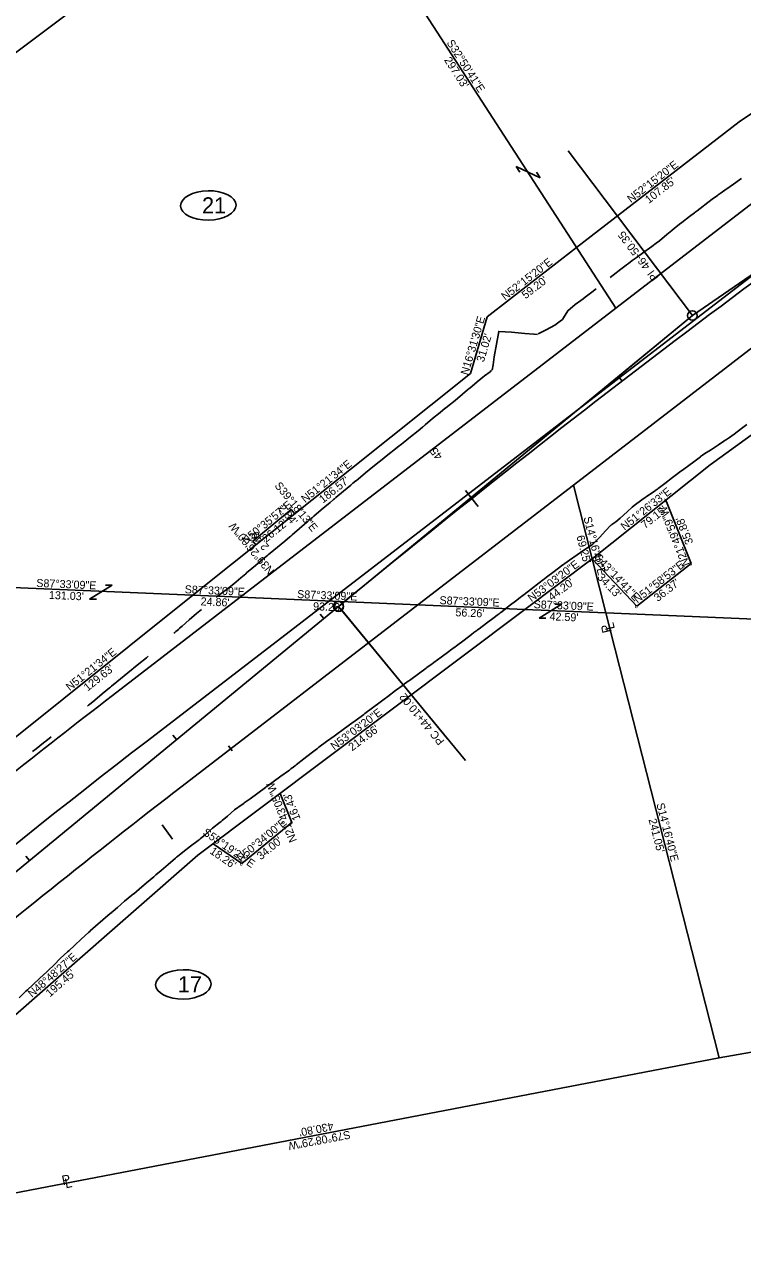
# Model space of a CAD drawing. Extents: x 1145508 to 2262867, y -3126236 to 2021677.
# Drawn here: x 1147661 to 1148038, y 2017346 to 2017985 of the extents above; entities that cross this region are included whole.
import ezdxf

# ---------------------------------------------------------------- set-up
doc = ezdxf.new("R2010")
doc.units = 0
for name, color, linetype in [('Default', 7, 'Continuous'), ('DSN_DRFT_Guideline-No-Plot', 7, 'Continuous'), ('DSN_RDWY_Alignment', 7, 'Continuous'), ('DSN_RDWY_Alignment Annotation', 7, 'Continuous'), ('DSN_RDWY_Const Limits', 7, 'Continuous'), ('DSN_ROW_Annotation', 7, 'Continuous'), ('DSN_ROW_Esmnt', 7, 'Continuous'), ('DSN_ROW_Line', 7, 'Continuous'), ('DSN_ROW_Line-Annotation', 7, 'Continuous'), ('DSN_ROW_Prop-Line', 7, 'Continuous'), ('DSN_ROW_Prop-Line-Annotation', 7, 'Continuous'), ('E_Const Align', 7, 'Continuous'), ('EX_QSECTION', 7, 'Continuous'), ('EX_ROW', 7, 'Continuous'), ('EX_ROW_ANNOT', 7, 'Continuous'), ('EX_SIGN', 7, 'Continuous')]:
    doc.layers.add(name, color=color, linetype=linetype)

msp = doc.modelspace()

# ---------------------------------------------------------------- linework, layer by layer
at = {"layer": 'Default'}
msp.add_line((1148336.03, 2018078.83), (1147725.18, 2017608.51), dxfattribs=at)
msp.add_arc((1150521.47, 2013976.61), 4583.66, 127.59365, 131.75523, dxfattribs=at)
at = {"layer": 'DSN_RDWY_Alignment'}
for p, q in [((1148011.14, 2017831.73), (1148208.89, 2017968.31)), ((1147825.51, 2017679.08), (1148011.14, 2017831.73))]:
    msp.add_line(p, q, dxfattribs=at)
for points in [[(1148011.14, 2017831.73), (1147945.95, 2017918.14)], [(1147825.51, 2017679.08), (1147892.09, 2017598.12)]]:
    msp.add_lwpolyline(points, dxfattribs=at)
for centre in [(1148011.14, 2017831.73), (1147825.51, 2017679.08)]:
    msp.add_circle(centre, 2.5, dxfattribs=at)
at = {"layer": 'DSN_RDWY_Alignment Annotation'}
for p, q in [((1148011.14, 2017831.73), (1147975, 2017879.63)), ((1147975, 2017879.63), (1147975, 2017879.63)), ((1148011.14, 2017831.73), (1148070.38, 2017872.65)), ((1148011.14, 2017831.73), (1147955.52, 2017786)), ((1147972.39, 2017799.68), (1147974.22, 2017797.3)), ((1147892.13, 2017739.86), (1147898.75, 2017731.56)), ((1147825.51, 2017679.08), (1147825.51, 2017679.08)), ((1147827.21, 2017677.02), (1147882.68, 2017609.57)), ((1147815.87, 2017675.03), (1147817.77, 2017672.72)), ((1147738.63, 2017611.52), (1147740.54, 2017609.2)), ((1147882.68, 2017609.57), (1147882.68, 2017609.57)), ((1147661.4, 2017548), (1147663.3, 2017545.68))]:
    msp.add_line(p, q, dxfattribs=at)
msp.add_circle((1147825.51, 2017679.08), 2.67, dxfattribs=at)
at = {"layer": 'DSN_RDWY_Const Limits'}
for points in [[(1147968.02, 2017851.67), (1147969.59, 2017852.97), (1147973.59, 2017856.04), (1147976.33, 2017858.15), (1147976.51, 2017858.28), (1147977.59, 2017859.11), (1147979.56, 2017860.62), (1147981.65, 2017862.09), (1147985.74, 2017865.05), (1147988.57, 2017867.1), (1147988.68, 2017867.18), (1147989.82, 2017868.01), (1147992.23, 2017869.76), (1147993.88, 2017870.99), (1147997.77, 2017874.22), (1148000.42, 2017876.43), (1148000.58, 2017876.56), (1148001.64, 2017877.45), (1148004.32, 2017879.68), (1148005.54, 2017880.65), (1148009.58, 2017883.66), (1148012.26, 2017885.71), (1148012.55, 2017885.93), (1148013.59, 2017886.73), (1148016.75, 2017889.14), (1148017.6, 2017889.79), (1148021.6, 2017892.85), (1148024.32, 2017894.82), (1148024.62, 2017895.03), (1148025.7, 2017895.79), (1148029.36, 2017898.37), (1148029.82, 2017898.69), (1148033.94, 2017901.6), (1148036.65, 2017903.51), (1148036.99, 2017903.76)], [(1147930.31, 2017822.15), (1147934.44, 2017824.26), (1147938.95, 2017826.66), (1147939.76, 2017827.26), (1147941.84, 2017828.78), (1147941.85, 2017828.79), (1147942.97, 2017829.7), (1147943.5, 2017830.61), (1147945.85, 2017834.22), (1147949.67, 2017837.52), (1147952.55, 2017839.59), (1147952.62, 2017839.64), (1147953.77, 2017840.46), (1147954.97, 2017841.34), (1147957.74, 2017843.57), (1147960.73, 2017845.85)], [(1147906.18, 2017803.13), (1147906.54, 2017805.93), (1147907.11, 2017810.13), (1147908.34, 2017816.76), (1147909.22, 2017821.47), (1147909.23, 2017821.53), (1147909.57, 2017823.36), (1147909.58, 2017823.39), (1147916.29, 2017822.98), (1147923.16, 2017822.36), (1147928.01, 2017821.92), (1147928.1, 2017821.91), (1147929.94, 2017821.83)], [(1147761.37, 2017683.84), (1147762.55, 2017684.76), (1147765.28, 2017686.81), (1147765.8, 2017687.2), (1147766.55, 2017687.77), (1147770.47, 2017690.88), (1147774.31, 2017694.08), (1147776.82, 2017696.23), (1147777.46, 2017696.78), (1147778.1, 2017697.34), (1147781.89, 2017700.6), (1147785.74, 2017703.79), (1147788.32, 2017705.92), (1147788.9, 2017706.4), (1147789.6, 2017706.98), (1147793.45, 2017710.16), (1147797.31, 2017713.34), (1147797.32, 2017713.35), (1147799.87, 2017715.51), (1147800.45, 2017716), (1147801.15, 2017716.61), (1147804.98, 2017719.89), (1147808.78, 2017723.2), (1147809.16, 2017723.54), (1147811.37, 2017725.43), (1147811.81, 2017725.81), (1147812.6, 2017726.48), (1147816.43, 2017729.76), (1147820.3, 2017732.99), (1147821.08, 2017733.64), (1147822.93, 2017735.2), (1147823.33, 2017735.53), (1147824.16, 2017736.23), (1147828.02, 2017739.47), (1147831.89, 2017742.69), (1147833.06, 2017743.67), (1147834.54, 2017744.91), (1147834.89, 2017745.2), (1147835.76, 2017745.93), (1147839.63, 2017749.16), (1147843.55, 2017752.33), (1147845.12, 2017753.59), (1147846.08, 2017754.35), (1147846.73, 2017754.87), (1147847.49, 2017755.47), (1147851.43, 2017758.61), (1147855.37, 2017761.75), (1147857.34, 2017763.32), (1147857.91, 2017763.77), (1147858.53, 2017764.26), (1147859.32, 2017764.89), (1147863.26, 2017768.02), (1147867.21, 2017771.15), (1147869.5, 2017773.12), (1147869.93, 2017773.5), (1147869.99, 2017773.56), (1147871.02, 2017774.46), (1147874.85, 2017777.73), (1147878.78, 2017780.9), (1147881.52, 2017783.11), (1147881.59, 2017783.17), (1147881.61, 2017783.18), (1147882.7, 2017784.06), (1147886.63, 2017787.22), (1147890.53, 2017790.41), (1147893.22, 2017792.72), (1147893.34, 2017792.83), (1147893.58, 2017793.03), (1147894.36, 2017793.7), (1147898.19, 2017796.98), (1147902.09, 2017800.18), (1147904.98, 2017802.26), (1147905.06, 2017802.32), (1147905.76, 2017802.82)], [(1147657.85, 2017473.59), (1147661.49, 2017477.04), (1147662.22, 2017477.73), (1147662.36, 2017477.86), (1147665.14, 2017480.47), (1147668.83, 2017483.85), (1147672.46, 2017487.31), (1147673.2, 2017488.01), (1147673.32, 2017488.12), (1147676.08, 2017490.78), (1147679.62, 2017494.34), (1147683.33, 2017497.71), (1147684.09, 2017498.39), (1147684.21, 2017498.5), (1147687.01, 2017501.1), (1147690.61, 2017504.6), (1147694.33, 2017507.94), (1147695.11, 2017508.64), (1147695.19, 2017508.72), (1147698.06, 2017511.28), (1147701.84, 2017514.56), (1147705.66, 2017517.79), (1147706.46, 2017518.46), (1147706.54, 2017518.53), (1147707.19, 2017519.08), (1147709.47, 2017521.03), (1147713.26, 2017524.28), (1147717.1, 2017527.49), (1147717.87, 2017528.13), (1147718.01, 2017528.25), (1147720.93, 2017530.7), (1147724.74, 2017533.94), (1147728.56, 2017537.18), (1147729.11, 2017537.65), (1147729.64, 2017538.1), (1147732.37, 2017540.41), (1147736.17, 2017543.66), (1147739.97, 2017546.91), (1147740.53, 2017547.38), (1147741.05, 2017547.83), (1147743.83, 2017550.09), (1147747.82, 2017553.12), (1147751.8, 2017556.14), (1147752.39, 2017556.58), (1147752.93, 2017556.99), (1147755.72, 2017559.25), (1147759.42, 2017562.63), (1147763.3, 2017565.77), (1147763.87, 2017566.23), (1147764.4, 2017566.66), (1147767.19, 2017568.91), (1147770.91, 2017572.27), (1147775.01, 2017575.15), (1147775.74, 2017575.65), (1147776.04, 2017575.86), (1147779.15, 2017577.99), (1147783.07, 2017581.09), (1147787.13, 2017584.02), (1147787.6, 2017584.36), (1147788.37, 2017584.92), (1147791.2, 2017586.96), (1147795.27, 2017589.87), (1147799.32, 2017592.83), (1147799.77, 2017593.18), (1147800.51, 2017593.75), (1147801.22, 2017594.3), (1147801.8, 2017594.75), (1147801.9, 2017594.83), (1147802.65, 2017595.41), (1147803.27, 2017595.89), (1147807.22, 2017598.96), (1147811.17, 2017602.02), (1147813.88, 2017604.12), (1147814.39, 2017604.52), (1147815.12, 2017605.09), (1147819.15, 2017608.07), (1147823.2, 2017611.01), (1147825.97, 2017613.02), (1147826.5, 2017613.4), (1147827.26, 2017613.95), (1147831.31, 2017616.89), (1147835.37, 2017619.83), (1147838.01, 2017621.82), (1147838.68, 2017622.34), (1147839.36, 2017622.85), (1147843.37, 2017625.85), (1147847.38, 2017628.85), (1147850.05, 2017630.85), (1147850.66, 2017631.3), (1147851.39, 2017631.84), (1147855.4, 2017634.83), (1147859.43, 2017637.8), (1147859.45, 2017637.81), (1147862.09, 2017639.76), (1147862.69, 2017640.21), (1147863.42, 2017640.75), (1147867.42, 2017643.69), (1147871.42, 2017646.62), (1147871.83, 2017646.92), (1147874.13, 2017648.61), (1147874.59, 2017648.95), (1147875.42, 2017649.55), (1147879.42, 2017652.48), (1147883.41, 2017655.42), (1147884.22, 2017656.02), (1147886.13, 2017657.43), (1147886.54, 2017657.74), (1147887.39, 2017658.38), (1147891.33, 2017661.38), (1147895.27, 2017664.38), (1147896.46, 2017665.28), (1147897.97, 2017666.43), (1147898.34, 2017666.7), (1147899.22, 2017667.37), (1147903.21, 2017670.32), (1147907.2, 2017673.25), (1147908.77, 2017674.47), (1147909.72, 2017675.2), (1147910.37, 2017675.7), (1147911.12, 2017676.28), (1147915.04, 2017679.3), (1147918.96, 2017682.33), (1147920.92, 2017683.83), (1147921.49, 2017684.27), (1147922.11, 2017684.74), (1147922.89, 2017685.35), (1147926.82, 2017688.36), (1147930.75, 2017691.37), (1147933.11, 2017693.17), (1147933.56, 2017693.51), (1147933.62, 2017693.56), (1147934.69, 2017694.37), (1147938.63, 2017697.37), (1147942.56, 2017700.37), (1147945.37, 2017702.4), (1147945.45, 2017702.45), (1147945.46, 2017702.47), (1147946.6, 2017703.25), (1147950.68, 2017706.06), (1147954.77, 2017708.88), (1147957.64, 2017710.85), (1147957.77, 2017710.94), (1147958.03, 2017711.11), (1147958.86, 2017711.68), (1147962.39, 2017715.2), (1147965.77, 2017718.91), (1147968.21, 2017721.47), (1147968.29, 2017721.53), (1147968.96, 2017722.04), (1147969.37, 2017722.35), (1147970.99, 2017723.48), (1147973.27, 2017725.39), (1147976.97, 2017728.7), (1147979.57, 2017731.09), (1147979.6, 2017731.12), (1147980.63, 2017732.03), (1147980.65, 2017732.04), (1147984.6, 2017735.02), (1147988.66, 2017737.87), (1147991.59, 2017739.8), (1147991.64, 2017739.84), (1147992.77, 2017740.64), (1147993.15, 2017740.93), (1147996.71, 2017743.64), (1148000.65, 2017746.64), (1148001.44, 2017747.24), (1148003.44, 2017748.79), (1148003.45, 2017748.79), (1148004.61, 2017749.62), (1148005.41, 2017750.16), (1148008.59, 2017752.56), (1148012.55, 2017755.53), (1148015.33, 2017757.62), (1148015.4, 2017757.67), (1148016.51, 2017758.5), (1148017.72, 2017759.31), (1148020.73, 2017761.13), (1148024.9, 2017763.83), (1148027.72, 2017765.8), (1148027.85, 2017765.89), (1148028.96, 2017766.67), (1148030.56, 2017767.78), (1148033.02, 2017769.5), (1148037, 2017772.45), (1148039.72, 2017774.48)], [(1147739.15, 2017665.02), (1147739.61, 2017665.43), (1147740.04, 2017665.8), (1147740.76, 2017666.41), (1147741.44, 2017666.99), (1147742, 2017667.46), (1147742.1, 2017667.55), (1147742.83, 2017668.16), (1147743.42, 2017668.66), (1147747.18, 2017671.97), (1147750.95, 2017675.26), (1147753.57, 2017677.45)], [(1147693.79, 2017626.68), (1147694.35, 2017627.16), (1147694.86, 2017627.6), (1147697.63, 2017629.89), (1147701.48, 2017633.08), (1147705.33, 2017636.26), (1147705.9, 2017636.73), (1147706.41, 2017637.16), (1147709.18, 2017639.45), (1147713.04, 2017642.63), (1147716.92, 2017645.79), (1147717.6, 2017646.34), (1147717.89, 2017646.58), (1147720.8, 2017648.94), (1147724.68, 2017652.1), (1147725.55, 2017652.86)], [(1147665.01, 2017602.86), (1147666.83, 2017604.36), (1147670.73, 2017607.49), (1147671.31, 2017607.94), (1147671.85, 2017608.38), (1147674.64, 2017610.61)]]:
    msp.add_lwpolyline(points, dxfattribs=at)
at = {"layer": 'DSN_ROW_Esmnt'}
for p, q in [((1148010.59, 2017701.56), (1147997.25, 2017734.86)), ((1147780.52, 2017713.29), (1147800.71, 2017729.87)), ((1147780.52, 2017713.29), (1147800.71, 2017729.87)), ((1147800.71, 2017729.87), (1147802.51, 2017727.68)), ((1147782.11, 2017711.36), (1147780.52, 2017713.29)), ((1147958.55, 2017704.02), (1147981.94, 2017679.16)), ((1147981.94, 2017679.16), (1148010.59, 2017701.56)), ((1147800.95, 2017565.66), (1147794.86, 2017580.92)), ((1147774.68, 2017544.06), (1147800.95, 2017565.66)), ((1147759.67, 2017554.45), (1147774.68, 2017544.06))]:
    msp.add_line(p, q, dxfattribs=at)
at = {"layer": 'DSN_ROW_Line'}
for p, q in [((1148035.64, 2017933.4), (1148226.66, 2018061.49)), ((1147950.36, 2017867.38), (1148035.64, 2017933.4)), ((1147903.55, 2017831.14), (1147950.36, 2017867.38)), ((1147894.72, 2017801.4), (1147903.55, 2017831.14)), ((1148020.45, 2017753.36), (1148124.6, 2017828.73)), ((1147749, 2017684.9), (1147894.72, 2017801.4)), ((1147958.55, 2017704.02), (1148020.45, 2017753.36)), ((1147923.23, 2017677.45), (1147958.55, 2017704.02)), ((1147647.75, 2017603.95), (1147749, 2017684.9)), ((1147751.67, 2017548.43), (1147923.23, 2017677.45)), ((1147604.59, 2017419.72), (1147751.67, 2017548.43))]:
    msp.add_line(p, q, dxfattribs=at)
at = {"layer": 'DSN_ROW_Line-Annotation'}
for centre in [(1147757.16, 2017889.53), (1147744.05, 2017480.64)]:
    msp.add_ellipse(centre, major_axis=(14.54, 0.23), ratio=0.529773, dxfattribs=at)
at = {"layer": 'DSN_ROW_Prop-Line'}
for p, q in [((1147627.67, 2017948.45), (1147809.8, 2018085.11)), ((1147809.8, 2018085.11), (1147970.9, 2017835.56)), ((1147948.7, 2017742.75), (1147965.78, 2017675.63)), ((1147965.78, 2017675.63), (1148025.23, 2017442.03)), ((1148025.23, 2017442.03), (1148128.19, 2017460.72)), ((1148025.23, 2017442.03), (1147602.14, 2017360.88))]:
    msp.add_line(p, q, dxfattribs=at)
at = {"layer": 'DSN_ROW_Prop-Line-Annotation'}
for p, q in [((1147920.59, 2017907.01), (1147918.64, 2017909.98)), ((1147918.64, 2017909.98), (1147931.32, 2017904.11)), ((1147931.32, 2017904.11), (1147929.37, 2017907.08)), ((1147694.87, 2017682.79), (1147706.73, 2017690.17)), ((1147706.73, 2017690.17), (1147703.18, 2017690.17)), ((1147698.42, 2017682.79), (1147694.87, 2017682.79)), ((1147930.68, 2017672.88), (1147942.53, 2017680.26)), ((1147942.53, 2017680.26), (1147938.99, 2017680.26)), ((1147934.22, 2017672.88), (1147930.68, 2017672.88))]:
    msp.add_line(p, q, dxfattribs=at)
at = {"layer": 'E_Const Align'}
msp.add_line((1146840, 2016868.61), (1147825.51, 2017679.08), dxfattribs=at)
msp.add_arc((1151464.82, 2013253.76), 5729.58, 124.62946, 129.43332, dxfattribs=at)
msp.add_arc((1151464.82, 2013253.76), 5729.58, 124.62946, 129.43332, dxfattribs=at)
at = {"layer": 'EX_QSECTION'}
for p, q in [((1147618.09, 2017690.49), (1147749, 2017684.9)), ((1147749, 2017684.9), (1147773.84, 2017683.84)), ((1147773.84, 2017683.84), (1147867.02, 2017679.86)), ((1147867.02, 2017679.86), (1147923.23, 2017677.45)), ((1147923.23, 2017677.45), (1147965.78, 2017675.63)), ((1147965.78, 2017675.63), (1148150.83, 2017667.72))]:
    msp.add_line(p, q, dxfattribs=at)
at = {"layer": 'EX_ROW'}
for p, q in [((1147970.9, 2017835.56), (1148239.28, 2018042.2)), ((1148142.01, 2017891.58), (1147948.7, 2017742.75)), ((1147773.84, 2017683.84), (1147970.9, 2017835.56)), ((1147867.02, 2017679.86), (1147948.7, 2017742.75)), ((1147706.88, 2017632.28), (1147773.84, 2017683.84)), ((1147743.48, 2017584.74), (1147867.02, 2017679.86))]:
    msp.add_line(p, q, dxfattribs=at)
for radius, end in [(4613.66, 128.49351), (4553.66, 129.79541)]:
    msp.add_arc((1150521.47, 2013976.61), radius, 127.59365, end, dxfattribs=at)
at = {"layer": 'EX_SIGN'}
for p, q in [((1147767.73, 2017605.84), (1147769.65, 2017603.29)), ((1147732.96, 2017564.33), (1147738.29, 2017556.79))]:
    msp.add_line(p, q, dxfattribs=at)

# ---------------------------------------------------------------- texts
at = {"layer": 'DSN_DRFT_Guideline-No-Plot'}
msp.add_text('b', height=2, dxfattribs=at).set_placement((1147996.25, 2017733.86))
at = {"layer": 'DSN_RDWY_Alignment Annotation'}
for s, rotation, p in [('46+50.35', 127.03139, (1147989.28, 2017857.71)), ('PI ', 127.03139, (1147993.74, 2017851.8)), ('45', 128.53348, (1147880.35, 2017758.02)), ('44+10.02', 129.43332, (1147875.25, 2017615.77)), ('PC', 129.43332, (1147881.29, 2017608.42))]:
    msp.add_text(s, height=4.2, rotation=rotation, dxfattribs=at).set_placement(p)
at = {"layer": 'DSN_ROW_Annotation'}
for s, rotation, p in [('S32°50\'41"E', 302.84462, (1147882.01, 2017974.91)), ("297.03'", 302.84462, (1147880.72, 2017965.85)), ('N52°15\'20"E', 37.74439, (1147978.96, 2017890.66)), ("107.85'", 37.74439, (1147988.33, 2017890.32)), ('N52°15\'20"E', 37.74439, (1147912.91, 2017839.53)), ("59.20'", 37.74439, (1147923.63, 2017840.23)), ('N16°31\'30"E', 73.47509, (1147893.42, 2017800.17)), ("31.02'", 73.47509, (1147901.71, 2017807)), ('N51°21\'34"E', 38.64061, (1147807.98, 2017733.2)), ("186.57'", 38.64061, (1147817.35, 2017733.01)), ('S39°18\'13"E', 309.30348, (1147791.69, 2017742.32)), ('N51°26\'33"E', 38.55752, (1147975.6, 2017718.76)), ('N50°35\'57"E', 39.40075, (1147776.86, 2017711.45)), ('N50°35\'57"E', 39.40075, (1147776.86, 2017711.45)), ("2.84'", 309.30348, (1147793.58, 2017730.53)), ("79.15'", 38.55752, (1147986.31, 2017719.62)), ('N21°49\'59"W', 111.83319, (1148009.8, 2017701.11)), ('N39°26\'00"W', 129.43332, (1147792.09, 2017697.8)), ("26.12'", 39.40075, (1147787.55, 2017712.47)), ("26.12'", 39.40075, (1147787.55, 2017712.47)), ('S14°16\'40"E', 284.27767, (1147953.98, 2017725.66)), ("35.88'", 111.83319, (1148011.68, 2017712.54)), ("2.49'", 129.43332, (1147789.35, 2017710.59)), ("69.25'", 284.27767, (1147950.29, 2017715.83)), ('N53°03\'20"E', 36.94437, (1147926.72, 2017681.21)), ('S43°14\'41"E', 313.24464, (1147959.42, 2017704.42)), ('N51°58\'53"E', 38.01848, (1147982.27, 2017680.56)), ("34.13'", 313.24464, (1147960.95, 2017694.04)), ("44.20'", 36.94437, (1147937.44, 2017681.76)), ("36.37'", 38.01848, (1147992.98, 2017681.32)), ('N51°21\'34"E', 38.64061, (1147684.49, 2017634.48)), ("129.63'", 38.64061, (1147693.86, 2017634.29)), ('N53°03\'20"E', 36.94437, (1147823.27, 2017603.41)), ("214.66'", 36.94437, (1147832.63, 2017602.94)), ('N21°43\'05"W', 111.71813, (1147803.75, 2017556.17)), ("16.43'", 111.71813, (1147805.66, 2017567.6)), ('S14°16\'40"E', 284.27767, (1147992.24, 2017575.3)), ('S55°19\'21"E', 325.32242, (1147753.9, 2017559.53)), ('N50°34\'00"E', 39.43332, (1147774.07, 2017544.72)), ("241.05'", 284.27767, (1147988.13, 2017567.13)), ("34.00'", 39.43332, (1147784.76, 2017545.74)), ("18.26'", 325.32242, (1147757.57, 2017549.7)), ('N48°48\'27"E', 41.19253, (1147664.7, 2017473.52)), ("195.45'", 41.19253, (1147674.07, 2017473.75)), ('S79°08\'29"W', 190.85863, (1147831.3, 2017403.92)), ("430.80'", 190.85863, (1147822.4, 2017408.32))]:
    msp.add_text(s, height=4.2, rotation=rotation, dxfattribs=at).set_placement(p)
at = {"layer": 'DSN_ROW_Esmnt'}
for p in [(1147799.71, 2017728.87), (1147779.52, 2017712.29), (1148009.59, 2017700.56), (1147980.94, 2017678.16), (1147799.95, 2017564.66), (1147773.68, 2017543.06)]:
    msp.add_text('b', height=2, dxfattribs=at).set_placement(p)
at = {"layer": 'DSN_ROW_Line-Annotation'}
for s, p in [('21', (1147753.87, 2017885.32)), ('17', (1147741.18, 2017476.43))]:
    msp.add_text(s, height=8.5, dxfattribs=at).set_placement(p)
at = {"layer": 'DSN_ROW_Prop-Line-Annotation'}
for s, rotation, p in [('L', 103.46574, (1147970.53, 2017667.36)), ('P', 103.46574, (1147968.94, 2017665.78)), ('P', 11.6533, (1147680.87, 2017375.19)), ('L', 11.6533, (1147682.4, 2017373.55))]:
    msp.add_text(s, height=5, rotation=rotation, dxfattribs=at).set_placement(p)
at = {"layer": 'EX_ROW_ANNOT'}
for s, p in [('S87°33\'09"E', (1147666.84, 2017689.31)), ('S87°33\'09"E', (1147666.84, 2017689.31)), ('S87°33\'09"E', (1147744.71, 2017685.98)), ('S87°33\'09"E', (1147744.71, 2017685.98)), ("131.03'", (1147673.48, 2017683.02)), ("131.03'", (1147673.48, 2017683.02)), ("24.86'", (1147753.06, 2017679.62)), ("24.86'", (1147753.06, 2017679.62)), ('S87°33\'09"E', (1147803.72, 2017683.46)), ('S87°33\'09"E', (1147803.72, 2017683.46)), ('S87°33\'09"E', (1147878.41, 2017680.27)), ('S87°33\'09"E', (1147878.41, 2017680.27)), ("93.26'", (1147812.06, 2017677.1)), ("93.26'", (1147812.06, 2017677.1)), ("56.26'", (1147886.76, 2017673.91)), ("56.26'", (1147886.76, 2017673.91)), ('S87°33\'09"E', (1147927.79, 2017678.16)), ('S87°33\'09"E', (1147927.79, 2017678.16)), ("42.59'", (1147936.14, 2017671.8)), ("42.59'", (1147936.14, 2017671.8))]:
    msp.add_text(s, height=4.2, rotation=357.55261, dxfattribs=at).set_placement(p)

doc.saveas('drawing.dxf')
